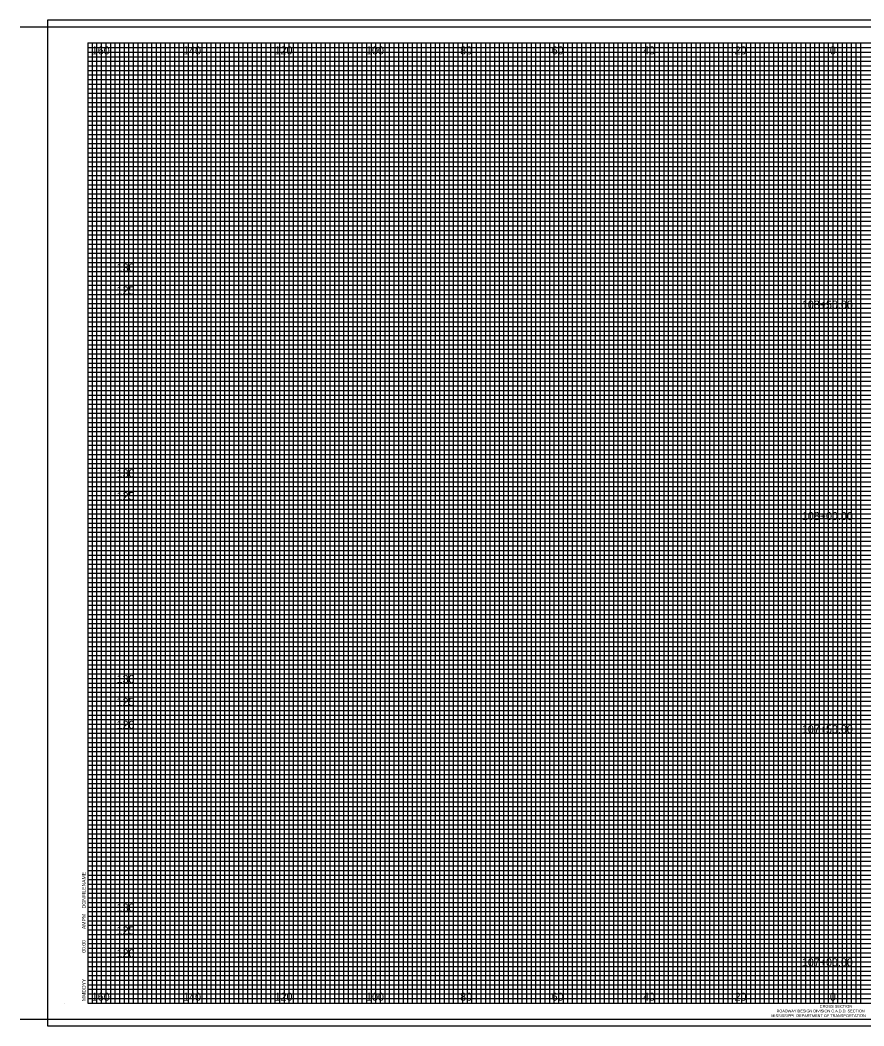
# Model space of a CAD drawing. Extents: x -3604 to 2303, y -13 to 9543.
# Drawn here: x -3604.5 to -3420, y 7374.1 to 7594.1 of the extents above; entities that cross this region are included whole.
import ezdxf

# ---------------------------------------------------------------- set-up
doc = ezdxf.new("R2010")
doc.units = 0
for name, color, linetype in [('SHEET_BORDER', 7, 'Continuous'), ('SHEET_BORDER_TX', 7, 'Continuous'), ('SHEET_DATE_DGN_TX', 7, 'Continuous'), ('SHEET_PLOTTING_SHAPE', 7, 'Continuous'), ('XS_SHEET_LABELS_ELEVATION', 7, 'Continuous'), ('XS_SHEET_LABELS_OFFSET', 7, 'Continuous'), ('XS_SHEET_LABELS_STATION', 7, 'Continuous'), ('XS_SHEET_MAJOR_GRIDS', 7, 'Continuous'), ('XS_SHEET_MEDIUM_GRIDS', 7, 'Continuous'), ('XS_SHEET_MINOR_GRIDS', 7, 'Continuous')]:
    doc.layers.add(name, color=color, linetype=linetype)

msp = doc.modelspace()

# ---------------------------------------------------------------- linework, layer by layer
at = {"layer": 'SHEET_BORDER'}
for p, q in [((-3604.48, 7592.59), (-3252.48, 7592.59)), ((-3589.68, 7589.09), (-3254.68, 7589.09)), ((-3589.68, 7589.09), (-3589.68, 7379.09)), ((-3445.68, 7379.09), (-3445.68, 7589.09)), ((-3594.68, 7379.09), (-3594.68, 7379.09)), ((-3589.68, 7379.09), (-3254.68, 7379.09)), ((-3604.48, 7375.59), (-3252.48, 7375.59))]:
    msp.add_line(p, q, dxfattribs=at)
at = {"layer": 'SHEET_PLOTTING_SHAPE'}
msp.add_lwpolyline([(-3598.48, 7374.09), (-3252.48, 7374.09), (-3252.48, 7594.09), (-3598.48, 7594.09)], close=True, dxfattribs=at)
at = {"layer": 'XS_SHEET_MAJOR_GRIDS'}
for p, q in [((-3584.68, 7379.09), (-3584.68, 7589.09)), ((-3574.68, 7379.09), (-3574.68, 7589.09)), ((-3564.68, 7379.09), (-3564.68, 7589.09)), ((-3554.68, 7379.09), (-3554.68, 7589.09)), ((-3544.68, 7379.09), (-3544.68, 7589.09)), ((-3534.68, 7379.09), (-3534.68, 7589.09)), ((-3524.68, 7379.09), (-3524.68, 7589.09)), ((-3514.68, 7379.09), (-3514.68, 7589.09)), ((-3504.68, 7379.09), (-3504.68, 7589.09)), ((-3494.68, 7379.09), (-3494.68, 7589.09)), ((-3484.68, 7379.09), (-3484.68, 7589.09)), ((-3474.68, 7379.09), (-3474.68, 7589.09)), ((-3464.68, 7379.09), (-3464.68, 7589.09)), ((-3454.68, 7379.09), (-3454.68, 7589.09)), ((-3444.68, 7379.09), (-3444.68, 7589.09)), ((-3434.68, 7379.09), (-3434.68, 7589.09)), ((-3424.68, 7379.09), (-3424.68, 7589.09)), ((-3589.68, 7579.09), (-3254.68, 7579.09)), ((-3589.68, 7569.09), (-3254.68, 7569.09)), ((-3589.68, 7559.09), (-3254.68, 7559.09)), ((-3589.68, 7549.09), (-3254.68, 7549.09)), ((-3589.68, 7539.09), (-3254.68, 7539.09)), ((-3589.68, 7529.09), (-3254.68, 7529.09)), ((-3589.68, 7519.09), (-3254.68, 7519.09)), ((-3589.68, 7509.09), (-3254.68, 7509.09)), ((-3589.68, 7499.09), (-3254.68, 7499.09)), ((-3589.68, 7489.09), (-3254.68, 7489.09)), ((-3589.68, 7479.09), (-3254.68, 7479.09)), ((-3589.68, 7469.09), (-3254.68, 7469.09)), ((-3589.68, 7459.09), (-3254.68, 7459.09)), ((-3589.68, 7449.09), (-3254.68, 7449.09)), ((-3589.68, 7439.09), (-3254.68, 7439.09)), ((-3589.68, 7429.09), (-3254.68, 7429.09)), ((-3589.68, 7419.09), (-3254.68, 7419.09)), ((-3589.68, 7409.09), (-3254.68, 7409.09)), ((-3589.68, 7399.09), (-3254.68, 7399.09)), ((-3589.68, 7389.09), (-3254.68, 7389.09))]:
    msp.add_line(p, q, dxfattribs=at)
at = {"layer": 'XS_SHEET_MEDIUM_GRIDS'}
for p, q in [((-3579.68, 7379.09), (-3579.68, 7589.09)), ((-3569.68, 7379.09), (-3569.68, 7589.09)), ((-3559.68, 7379.09), (-3559.68, 7589.09)), ((-3549.68, 7379.09), (-3549.68, 7589.09)), ((-3539.68, 7379.09), (-3539.68, 7589.09)), ((-3529.68, 7379.09), (-3529.68, 7589.09)), ((-3519.68, 7379.09), (-3519.68, 7589.09)), ((-3509.68, 7379.09), (-3509.68, 7589.09)), ((-3499.68, 7379.09), (-3499.68, 7589.09)), ((-3489.68, 7379.09), (-3489.68, 7589.09)), ((-3479.68, 7379.09), (-3479.68, 7589.09)), ((-3469.68, 7379.09), (-3469.68, 7589.09)), ((-3459.68, 7379.09), (-3459.68, 7589.09)), ((-3449.68, 7379.09), (-3449.68, 7589.09)), ((-3439.68, 7379.09), (-3439.68, 7589.09)), ((-3429.68, 7379.09), (-3429.68, 7589.09)), ((-3589.68, 7584.09), (-3281.68, 7584.09)), ((-3589.68, 7574.09), (-3254.68, 7574.09)), ((-3589.68, 7564.09), (-3254.68, 7564.09)), ((-3589.68, 7554.09), (-3254.68, 7554.09)), ((-3589.68, 7544.09), (-3254.68, 7544.09)), ((-3589.68, 7534.09), (-3254.68, 7534.09)), ((-3589.68, 7524.09), (-3254.68, 7524.09)), ((-3589.68, 7514.09), (-3254.68, 7514.09)), ((-3589.68, 7504.09), (-3254.68, 7504.09)), ((-3589.68, 7494.09), (-3254.68, 7494.09)), ((-3589.68, 7484.09), (-3254.68, 7484.09)), ((-3589.68, 7474.09), (-3254.68, 7474.09)), ((-3589.68, 7464.09), (-3254.68, 7464.09)), ((-3589.68, 7454.09), (-3254.68, 7454.09)), ((-3589.68, 7444.09), (-3254.68, 7444.09)), ((-3589.68, 7434.09), (-3254.68, 7434.09)), ((-3589.68, 7424.09), (-3254.68, 7424.09)), ((-3589.68, 7414.09), (-3254.68, 7414.09)), ((-3589.68, 7404.09), (-3254.68, 7404.09)), ((-3589.68, 7394.09), (-3254.68, 7394.09)), ((-3589.68, 7384.09), (-3264.68, 7384.09))]:
    msp.add_line(p, q, dxfattribs=at)
at = {"layer": 'XS_SHEET_MINOR_GRIDS'}
for p, q in [((-3589.68, 7588.09), (-3281.68, 7588.09)), ((-3588.68, 7379.09), (-3588.68, 7589.09)), ((-3587.68, 7379.09), (-3587.68, 7589.09)), ((-3586.68, 7379.09), (-3586.68, 7589.09)), ((-3585.68, 7379.09), (-3585.68, 7589.09)), ((-3583.68, 7379.09), (-3583.68, 7589.09)), ((-3582.68, 7379.09), (-3582.68, 7589.09)), ((-3581.68, 7379.09), (-3581.68, 7589.09)), ((-3580.68, 7379.09), (-3580.68, 7589.09)), ((-3578.68, 7379.09), (-3578.68, 7589.09)), ((-3577.68, 7379.09), (-3577.68, 7589.09)), ((-3576.68, 7379.09), (-3576.68, 7589.09)), ((-3575.68, 7379.09), (-3575.68, 7589.09)), ((-3573.68, 7379.09), (-3573.68, 7589.09)), ((-3572.68, 7379.09), (-3572.68, 7589.09)), ((-3571.68, 7379.09), (-3571.68, 7589.09)), ((-3570.68, 7379.09), (-3570.68, 7589.09)), ((-3568.68, 7379.09), (-3568.68, 7589.09)), ((-3567.68, 7379.09), (-3567.68, 7589.09)), ((-3566.68, 7379.09), (-3566.68, 7589.09)), ((-3565.68, 7379.09), (-3565.68, 7589.09)), ((-3563.68, 7379.09), (-3563.68, 7589.09)), ((-3562.68, 7379.09), (-3562.68, 7589.09)), ((-3561.68, 7379.09), (-3561.68, 7589.09)), ((-3560.68, 7379.09), (-3560.68, 7589.09)), ((-3558.68, 7379.09), (-3558.68, 7589.09)), ((-3557.68, 7379.09), (-3557.68, 7589.09)), ((-3556.68, 7379.09), (-3556.68, 7589.09)), ((-3555.68, 7379.09), (-3555.68, 7589.09)), ((-3553.68, 7379.09), (-3553.68, 7589.09)), ((-3552.68, 7379.09), (-3552.68, 7589.09)), ((-3551.68, 7379.09), (-3551.68, 7589.09)), ((-3550.68, 7379.09), (-3550.68, 7589.09)), ((-3548.68, 7379.09), (-3548.68, 7589.09)), ((-3547.68, 7379.09), (-3547.68, 7589.09)), ((-3546.68, 7379.09), (-3546.68, 7589.09)), ((-3545.68, 7379.09), (-3545.68, 7589.09)), ((-3543.68, 7379.09), (-3543.68, 7589.09)), ((-3542.68, 7379.09), (-3542.68, 7589.09)), ((-3541.68, 7379.09), (-3541.68, 7589.09)), ((-3540.68, 7379.09), (-3540.68, 7589.09)), ((-3538.68, 7379.09), (-3538.68, 7589.09)), ((-3537.68, 7379.09), (-3537.68, 7589.09)), ((-3536.68, 7379.09), (-3536.68, 7589.09)), ((-3535.68, 7379.09), (-3535.68, 7589.09)), ((-3533.68, 7379.09), (-3533.68, 7589.09)), ((-3532.68, 7379.09), (-3532.68, 7589.09)), ((-3531.68, 7379.09), (-3531.68, 7589.09)), ((-3530.68, 7379.09), (-3530.68, 7589.09)), ((-3528.68, 7379.09), (-3528.68, 7589.09)), ((-3527.68, 7379.09), (-3527.68, 7589.09)), ((-3526.68, 7379.09), (-3526.68, 7589.09)), ((-3525.68, 7379.09), (-3525.68, 7589.09)), ((-3523.68, 7379.09), (-3523.68, 7589.09)), ((-3522.68, 7379.09), (-3522.68, 7589.09)), ((-3521.68, 7379.09), (-3521.68, 7589.09)), ((-3520.68, 7379.09), (-3520.68, 7589.09)), ((-3518.68, 7379.09), (-3518.68, 7589.09)), ((-3517.68, 7379.09), (-3517.68, 7589.09)), ((-3516.68, 7379.09), (-3516.68, 7589.09)), ((-3515.68, 7379.09), (-3515.68, 7589.09)), ((-3513.68, 7379.09), (-3513.68, 7589.09)), ((-3512.68, 7379.09), (-3512.68, 7589.09)), ((-3511.68, 7379.09), (-3511.68, 7589.09)), ((-3510.68, 7379.09), (-3510.68, 7589.09)), ((-3508.68, 7379.09), (-3508.68, 7589.09)), ((-3507.68, 7379.09), (-3507.68, 7589.09)), ((-3506.68, 7379.09), (-3506.68, 7589.09)), ((-3505.68, 7379.09), (-3505.68, 7589.09)), ((-3503.68, 7379.09), (-3503.68, 7589.09)), ((-3502.68, 7379.09), (-3502.68, 7589.09)), ((-3501.68, 7379.09), (-3501.68, 7589.09)), ((-3500.68, 7379.09), (-3500.68, 7589.09)), ((-3498.68, 7379.09), (-3498.68, 7589.09)), ((-3497.68, 7379.09), (-3497.68, 7589.09)), ((-3496.68, 7379.09), (-3496.68, 7589.09)), ((-3495.68, 7379.09), (-3495.68, 7589.09)), ((-3493.68, 7379.09), (-3493.68, 7589.09)), ((-3492.68, 7379.09), (-3492.68, 7589.09)), ((-3491.68, 7379.09), (-3491.68, 7589.09)), ((-3490.68, 7379.09), (-3490.68, 7589.09)), ((-3488.68, 7379.09), (-3488.68, 7589.09)), ((-3487.68, 7379.09), (-3487.68, 7589.09)), ((-3486.68, 7379.09), (-3486.68, 7589.09)), ((-3485.68, 7379.09), (-3485.68, 7589.09)), ((-3483.68, 7379.09), (-3483.68, 7589.09)), ((-3482.68, 7379.09), (-3482.68, 7589.09)), ((-3481.68, 7379.09), (-3481.68, 7589.09)), ((-3480.68, 7379.09), (-3480.68, 7589.09)), ((-3478.68, 7379.09), (-3478.68, 7589.09)), ((-3477.68, 7379.09), (-3477.68, 7589.09)), ((-3476.68, 7379.09), (-3476.68, 7589.09)), ((-3475.68, 7379.09), (-3475.68, 7589.09)), ((-3473.68, 7379.09), (-3473.68, 7589.09)), ((-3472.68, 7379.09), (-3472.68, 7589.09)), ((-3471.68, 7379.09), (-3471.68, 7589.09)), ((-3470.68, 7379.09), (-3470.68, 7589.09)), ((-3468.68, 7379.09), (-3468.68, 7589.09)), ((-3467.68, 7379.09), (-3467.68, 7589.09)), ((-3466.68, 7379.09), (-3466.68, 7589.09)), ((-3465.68, 7379.09), (-3465.68, 7589.09)), ((-3463.68, 7379.09), (-3463.68, 7589.09)), ((-3462.68, 7379.09), (-3462.68, 7589.09)), ((-3461.68, 7379.09), (-3461.68, 7589.09)), ((-3460.68, 7379.09), (-3460.68, 7589.09)), ((-3458.68, 7379.09), (-3458.68, 7589.09)), ((-3457.68, 7379.09), (-3457.68, 7589.09)), ((-3456.68, 7379.09), (-3456.68, 7589.09)), ((-3455.68, 7379.09), (-3455.68, 7589.09)), ((-3453.68, 7379.09), (-3453.68, 7589.09)), ((-3452.68, 7379.09), (-3452.68, 7589.09)), ((-3451.68, 7379.09), (-3451.68, 7589.09)), ((-3450.68, 7379.09), (-3450.68, 7589.09)), ((-3448.68, 7379.09), (-3448.68, 7589.09)), ((-3447.68, 7379.09), (-3447.68, 7589.09)), ((-3446.68, 7379.09), (-3446.68, 7589.09)), ((-3443.68, 7379.09), (-3443.68, 7589.09)), ((-3442.68, 7379.09), (-3442.68, 7589.09)), ((-3441.68, 7379.09), (-3441.68, 7589.09)), ((-3440.68, 7379.09), (-3440.68, 7589.09)), ((-3438.68, 7379.09), (-3438.68, 7589.09)), ((-3437.68, 7379.09), (-3437.68, 7589.09)), ((-3436.68, 7379.09), (-3436.68, 7589.09)), ((-3435.68, 7379.09), (-3435.68, 7589.09)), ((-3433.68, 7379.09), (-3433.68, 7589.09)), ((-3432.68, 7379.09), (-3432.68, 7589.09)), ((-3431.68, 7379.09), (-3431.68, 7589.09)), ((-3430.68, 7379.09), (-3430.68, 7589.09)), ((-3428.68, 7379.09), (-3428.68, 7589.09)), ((-3427.68, 7379.09), (-3427.68, 7589.09)), ((-3426.68, 7379.09), (-3426.68, 7589.09)), ((-3425.68, 7379.09), (-3425.68, 7589.09)), ((-3423.68, 7379.09), (-3423.68, 7589.09)), ((-3422.68, 7379.09), (-3422.68, 7589.09)), ((-3421.68, 7379.09), (-3421.68, 7589.09)), ((-3420.68, 7379.09), (-3420.68, 7589.09)), ((-3589.68, 7587.09), (-3281.68, 7587.09)), ((-3589.68, 7586.09), (-3281.68, 7586.09)), ((-3589.68, 7585.09), (-3281.68, 7585.09)), ((-3589.68, 7583.09), (-3281.68, 7583.09)), ((-3589.68, 7582.09), (-3281.68, 7582.09)), ((-3589.68, 7581.09), (-3281.68, 7581.09)), ((-3589.68, 7580.09), (-3254.68, 7580.09)), ((-3589.68, 7578.09), (-3254.68, 7578.09)), ((-3589.68, 7577.09), (-3254.68, 7577.09)), ((-3589.68, 7576.09), (-3254.68, 7576.09)), ((-3589.68, 7575.09), (-3254.68, 7575.09)), ((-3589.68, 7573.09), (-3254.68, 7573.09)), ((-3589.68, 7572.09), (-3254.68, 7572.09)), ((-3589.68, 7571.09), (-3254.68, 7571.09)), ((-3589.68, 7570.09), (-3254.68, 7570.09)), ((-3589.68, 7568.09), (-3254.68, 7568.09)), ((-3589.68, 7567.09), (-3254.68, 7567.09)), ((-3589.68, 7566.09), (-3254.68, 7566.09)), ((-3589.68, 7565.09), (-3254.68, 7565.09)), ((-3589.68, 7563.09), (-3254.68, 7563.09)), ((-3589.68, 7562.09), (-3254.68, 7562.09)), ((-3589.68, 7561.09), (-3254.68, 7561.09)), ((-3589.68, 7560.09), (-3254.68, 7560.09)), ((-3589.68, 7558.09), (-3254.68, 7558.09)), ((-3589.68, 7557.09), (-3254.68, 7557.09)), ((-3589.68, 7556.09), (-3254.68, 7556.09)), ((-3589.68, 7555.09), (-3254.68, 7555.09)), ((-3589.68, 7553.09), (-3254.68, 7553.09)), ((-3589.68, 7552.09), (-3254.68, 7552.09)), ((-3589.68, 7551.09), (-3254.68, 7551.09)), ((-3589.68, 7550.09), (-3254.68, 7550.09)), ((-3589.68, 7548.09), (-3254.68, 7548.09)), ((-3589.68, 7547.09), (-3254.68, 7547.09)), ((-3589.68, 7546.09), (-3254.68, 7546.09)), ((-3589.68, 7545.09), (-3254.68, 7545.09)), ((-3589.68, 7543.09), (-3254.68, 7543.09)), ((-3589.68, 7542.09), (-3254.68, 7542.09)), ((-3589.68, 7541.09), (-3254.68, 7541.09)), ((-3589.68, 7540.09), (-3254.68, 7540.09)), ((-3589.68, 7538.09), (-3254.68, 7538.09)), ((-3589.68, 7537.09), (-3254.68, 7537.09)), ((-3589.68, 7536.09), (-3254.68, 7536.09)), ((-3589.68, 7535.09), (-3254.68, 7535.09)), ((-3589.68, 7533.09), (-3254.68, 7533.09)), ((-3589.68, 7532.09), (-3254.68, 7532.09)), ((-3589.68, 7531.09), (-3254.68, 7531.09)), ((-3589.68, 7530.09), (-3254.68, 7530.09)), ((-3589.68, 7528.09), (-3254.68, 7528.09)), ((-3589.68, 7527.09), (-3254.68, 7527.09)), ((-3589.68, 7526.09), (-3254.68, 7526.09)), ((-3589.68, 7525.09), (-3254.68, 7525.09)), ((-3589.68, 7523.09), (-3254.68, 7523.09)), ((-3589.68, 7522.09), (-3254.68, 7522.09)), ((-3589.68, 7521.09), (-3254.68, 7521.09)), ((-3589.68, 7520.09), (-3254.68, 7520.09)), ((-3589.68, 7518.09), (-3254.68, 7518.09)), ((-3589.68, 7517.09), (-3254.68, 7517.09)), ((-3589.68, 7516.09), (-3254.68, 7516.09)), ((-3589.68, 7515.09), (-3254.68, 7515.09)), ((-3589.68, 7513.09), (-3254.68, 7513.09)), ((-3589.68, 7512.09), (-3254.68, 7512.09)), ((-3589.68, 7511.09), (-3254.68, 7511.09)), ((-3589.68, 7510.09), (-3254.68, 7510.09)), ((-3589.68, 7508.09), (-3254.68, 7508.09)), ((-3589.68, 7507.09), (-3254.68, 7507.09)), ((-3589.68, 7506.09), (-3254.68, 7506.09)), ((-3589.68, 7505.09), (-3254.68, 7505.09)), ((-3589.68, 7503.09), (-3254.68, 7503.09)), ((-3589.68, 7502.09), (-3254.68, 7502.09)), ((-3589.68, 7501.09), (-3254.68, 7501.09)), ((-3589.68, 7500.09), (-3254.68, 7500.09)), ((-3589.68, 7498.09), (-3254.68, 7498.09)), ((-3589.68, 7497.09), (-3254.68, 7497.09)), ((-3589.68, 7496.09), (-3254.68, 7496.09)), ((-3589.68, 7495.09), (-3254.68, 7495.09)), ((-3589.68, 7493.09), (-3254.68, 7493.09)), ((-3589.68, 7492.09), (-3254.68, 7492.09)), ((-3589.68, 7491.09), (-3254.68, 7491.09)), ((-3589.68, 7490.09), (-3254.68, 7490.09)), ((-3589.68, 7488.09), (-3254.68, 7488.09)), ((-3589.68, 7487.09), (-3254.68, 7487.09)), ((-3589.68, 7486.09), (-3254.68, 7486.09)), ((-3589.68, 7485.09), (-3254.68, 7485.09)), ((-3589.68, 7483.09), (-3254.68, 7483.09)), ((-3589.68, 7482.09), (-3254.68, 7482.09)), ((-3589.68, 7481.09), (-3254.68, 7481.09)), ((-3589.68, 7480.09), (-3254.68, 7480.09)), ((-3589.68, 7478.09), (-3254.68, 7478.09)), ((-3589.68, 7477.09), (-3254.68, 7477.09)), ((-3589.68, 7476.09), (-3254.68, 7476.09)), ((-3589.68, 7475.09), (-3254.68, 7475.09)), ((-3589.68, 7473.09), (-3254.68, 7473.09)), ((-3589.68, 7472.09), (-3254.68, 7472.09)), ((-3589.68, 7471.09), (-3254.68, 7471.09)), ((-3589.68, 7470.09), (-3254.68, 7470.09)), ((-3589.68, 7468.09), (-3254.68, 7468.09)), ((-3589.68, 7467.09), (-3254.68, 7467.09)), ((-3589.68, 7466.09), (-3254.68, 7466.09)), ((-3589.68, 7465.09), (-3254.68, 7465.09)), ((-3589.68, 7463.09), (-3254.68, 7463.09)), ((-3589.68, 7462.09), (-3254.68, 7462.09)), ((-3589.68, 7461.09), (-3254.68, 7461.09)), ((-3589.68, 7460.09), (-3254.68, 7460.09)), ((-3589.68, 7458.09), (-3254.68, 7458.09)), ((-3589.68, 7457.09), (-3254.68, 7457.09)), ((-3589.68, 7456.09), (-3254.68, 7456.09)), ((-3589.68, 7455.09), (-3254.68, 7455.09)), ((-3589.68, 7453.09), (-3254.68, 7453.09)), ((-3589.68, 7452.09), (-3254.68, 7452.09)), ((-3589.68, 7451.09), (-3254.68, 7451.09)), ((-3589.68, 7450.09), (-3254.68, 7450.09)), ((-3589.68, 7448.09), (-3254.68, 7448.09)), ((-3589.68, 7447.09), (-3254.68, 7447.09)), ((-3589.68, 7446.09), (-3254.68, 7446.09)), ((-3589.68, 7445.09), (-3254.68, 7445.09)), ((-3589.68, 7443.09), (-3254.68, 7443.09)), ((-3589.68, 7442.09), (-3254.68, 7442.09)), ((-3589.68, 7441.09), (-3254.68, 7441.09)), ((-3589.68, 7440.09), (-3254.68, 7440.09)), ((-3589.68, 7438.09), (-3254.68, 7438.09)), ((-3589.68, 7437.09), (-3254.68, 7437.09)), ((-3589.68, 7436.09), (-3254.68, 7436.09)), ((-3589.68, 7435.09), (-3254.68, 7435.09)), ((-3589.68, 7433.09), (-3254.68, 7433.09)), ((-3589.68, 7432.09), (-3254.68, 7432.09)), ((-3589.68, 7431.09), (-3254.68, 7431.09)), ((-3589.68, 7430.09), (-3254.68, 7430.09)), ((-3589.68, 7428.09), (-3254.68, 7428.09)), ((-3589.68, 7427.09), (-3254.68, 7427.09)), ((-3589.68, 7426.09), (-3254.68, 7426.09)), ((-3589.68, 7425.09), (-3254.68, 7425.09)), ((-3589.68, 7423.09), (-3254.68, 7423.09)), ((-3589.68, 7422.09), (-3254.68, 7422.09)), ((-3589.68, 7421.09), (-3254.68, 7421.09)), ((-3589.68, 7420.09), (-3254.68, 7420.09)), ((-3589.68, 7418.09), (-3254.68, 7418.09)), ((-3589.68, 7417.09), (-3254.68, 7417.09)), ((-3589.68, 7416.09), (-3254.68, 7416.09)), ((-3589.68, 7415.09), (-3254.68, 7415.09)), ((-3589.68, 7413.09), (-3254.68, 7413.09)), ((-3589.68, 7412.09), (-3254.68, 7412.09)), ((-3589.68, 7411.09), (-3254.68, 7411.09)), ((-3589.68, 7410.09), (-3254.68, 7410.09)), ((-3589.68, 7408.09), (-3254.68, 7408.09)), ((-3589.68, 7407.09), (-3254.68, 7407.09)), ((-3589.68, 7406.09), (-3254.68, 7406.09)), ((-3589.68, 7405.09), (-3254.68, 7405.09)), ((-3589.68, 7403.09), (-3254.68, 7403.09)), ((-3589.68, 7402.09), (-3254.68, 7402.09)), ((-3589.68, 7401.09), (-3254.68, 7401.09)), ((-3589.68, 7400.09), (-3254.68, 7400.09)), ((-3589.68, 7400.09), (-3254.68, 7400.09)), ((-3589.68, 7400.09), (-3254.68, 7400.09)), ((-3589.68, 7398.09), (-3254.68, 7398.09)), ((-3589.68, 7397.09), (-3254.68, 7397.09)), ((-3589.68, 7396.09), (-3254.68, 7396.09)), ((-3589.68, 7395.09), (-3254.68, 7395.09)), ((-3589.68, 7393.09), (-3254.68, 7393.09)), ((-3589.68, 7392.09), (-3254.68, 7392.09)), ((-3589.68, 7391.09), (-3254.68, 7391.09)), ((-3589.68, 7390.09), (-3254.68, 7390.09)), ((-3589.68, 7388.09), (-3264.68, 7388.09)), ((-3589.68, 7387.09), (-3264.68, 7387.09)), ((-3589.68, 7386.09), (-3264.68, 7386.09)), ((-3589.68, 7385.09), (-3264.68, 7385.09)), ((-3589.68, 7385.09), (-3264.68, 7385.09)), ((-3589.68, 7385.09), (-3264.68, 7385.09)), ((-3589.68, 7383.09), (-3264.68, 7383.09)), ((-3589.68, 7382.09), (-3264.68, 7382.09)), ((-3589.68, 7381.09), (-3264.68, 7381.09)), ((-3589.68, 7380.09), (-3264.68, 7380.09))]:
    msp.add_line(p, q, dxfattribs=at)

# ---------------------------------------------------------------- texts
at = {"layer": 'SHEET_BORDER_TX'}
for s, height, p in [('MISSISSIPPI  DEPARTMENT OF TRANSPORTATION', 0.61, (-3440.24, 7376.01)), ('ROADWAY DESIGN DIVISION C.A.D.D. SECTION', 0.61, (-3439.08, 7377.04)), ('CROSS SECTION', 0.62, (-3429.64, 7378.06))]:
    msp.add_text(s, height=height, dxfattribs=at).set_placement(p)
at = {"layer": 'SHEET_DATE_DGN_TX'}
for s, p in [('DGNFILENAME', (-3590.15, 7399.79)), ('AMPM', (-3590.15, 7395.27)), ('00:00', (-3590.15, 7390.09)), ('MMDDYY', (-3590.15, 7379.51))]:
    msp.add_text(s, height=0.8, rotation=90, dxfattribs=at).set_placement(p)
at = {"layer": 'XS_SHEET_LABELS_ELEVATION'}
for s, p in [('  130  ', (-3584.68, 7539.09)), ('  125  ', (-3584.68, 7534.09)), ('  130  ', (-3584.68, 7494.09)), ('  125  ', (-3584.68, 7489.09)), ('  130  ', (-3584.68, 7449.09)), ('  125  ', (-3584.68, 7444.09)), ('  120  ', (-3584.68, 7439.09)), ('  130  ', (-3584.68, 7399.09)), ('  125  ', (-3584.68, 7394.09)), ('  120  ', (-3584.68, 7389.09))]:
    msp.add_text(s, height=1.75, dxfattribs=at).set_placement(p)
at = {"layer": 'XS_SHEET_LABELS_OFFSET'}
for s, p in [('  160  ', (-3590.11, 7586.59)), ('  140  ', (-3570.13, 7586.59)), ('  120  ', (-3550.13, 7586.59)), ('  100  ', (-3530.13, 7586.59)), ('  80  ', (-3509.56, 7586.59)), ('  60  ', (-3489.55, 7586.59)), ('  40  ', (-3469.56, 7586.59)), ('  20  ', (-3449.56, 7586.59)), ('  0  ', (-3428.71, 7586.59)), ('  0  ', (-3428.71, 7586.59)), ('  160  ', (-3590.11, 7379.59)), ('  140  ', (-3570.13, 7379.59)), ('  120  ', (-3550.13, 7379.59)), ('  100  ', (-3530.13, 7379.59)), ('  80  ', (-3509.56, 7379.59)), ('  60  ', (-3489.55, 7379.59)), ('  40  ', (-3469.56, 7379.59)), ('  20  ', (-3449.56, 7379.59)), ('  0  ', (-3428.71, 7379.59)), ('  0  ', (-3428.71, 7379.59))]:
    msp.add_text(s, height=1.75, dxfattribs=at).set_placement(p)
at = {"layer": 'XS_SHEET_LABELS_STATION'}
for s, p in [('  108+50.00  ', (-3434.83, 7530.98)), ('  108+00.00  ', (-3434.83, 7484.73)), ('  107+50.00  ', (-3434.83, 7438.11)), ('  107+00.00  ', (-3434.83, 7387.12))]:
    msp.add_text(s, height=1.75, dxfattribs=at).set_placement(p)

doc.saveas('drawing.dxf')
